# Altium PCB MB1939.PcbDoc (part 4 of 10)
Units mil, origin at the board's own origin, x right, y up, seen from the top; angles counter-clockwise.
Board outline 5910.64 x 4335.93 mil, 6 copper layers (Top Layer, l2_GND, L3_SIG, L4_VCC, L5_GND, Bottom Layer), stack 58.424 mil thick; 635 components, 489 nets, 2289 pads, 1388 vias.
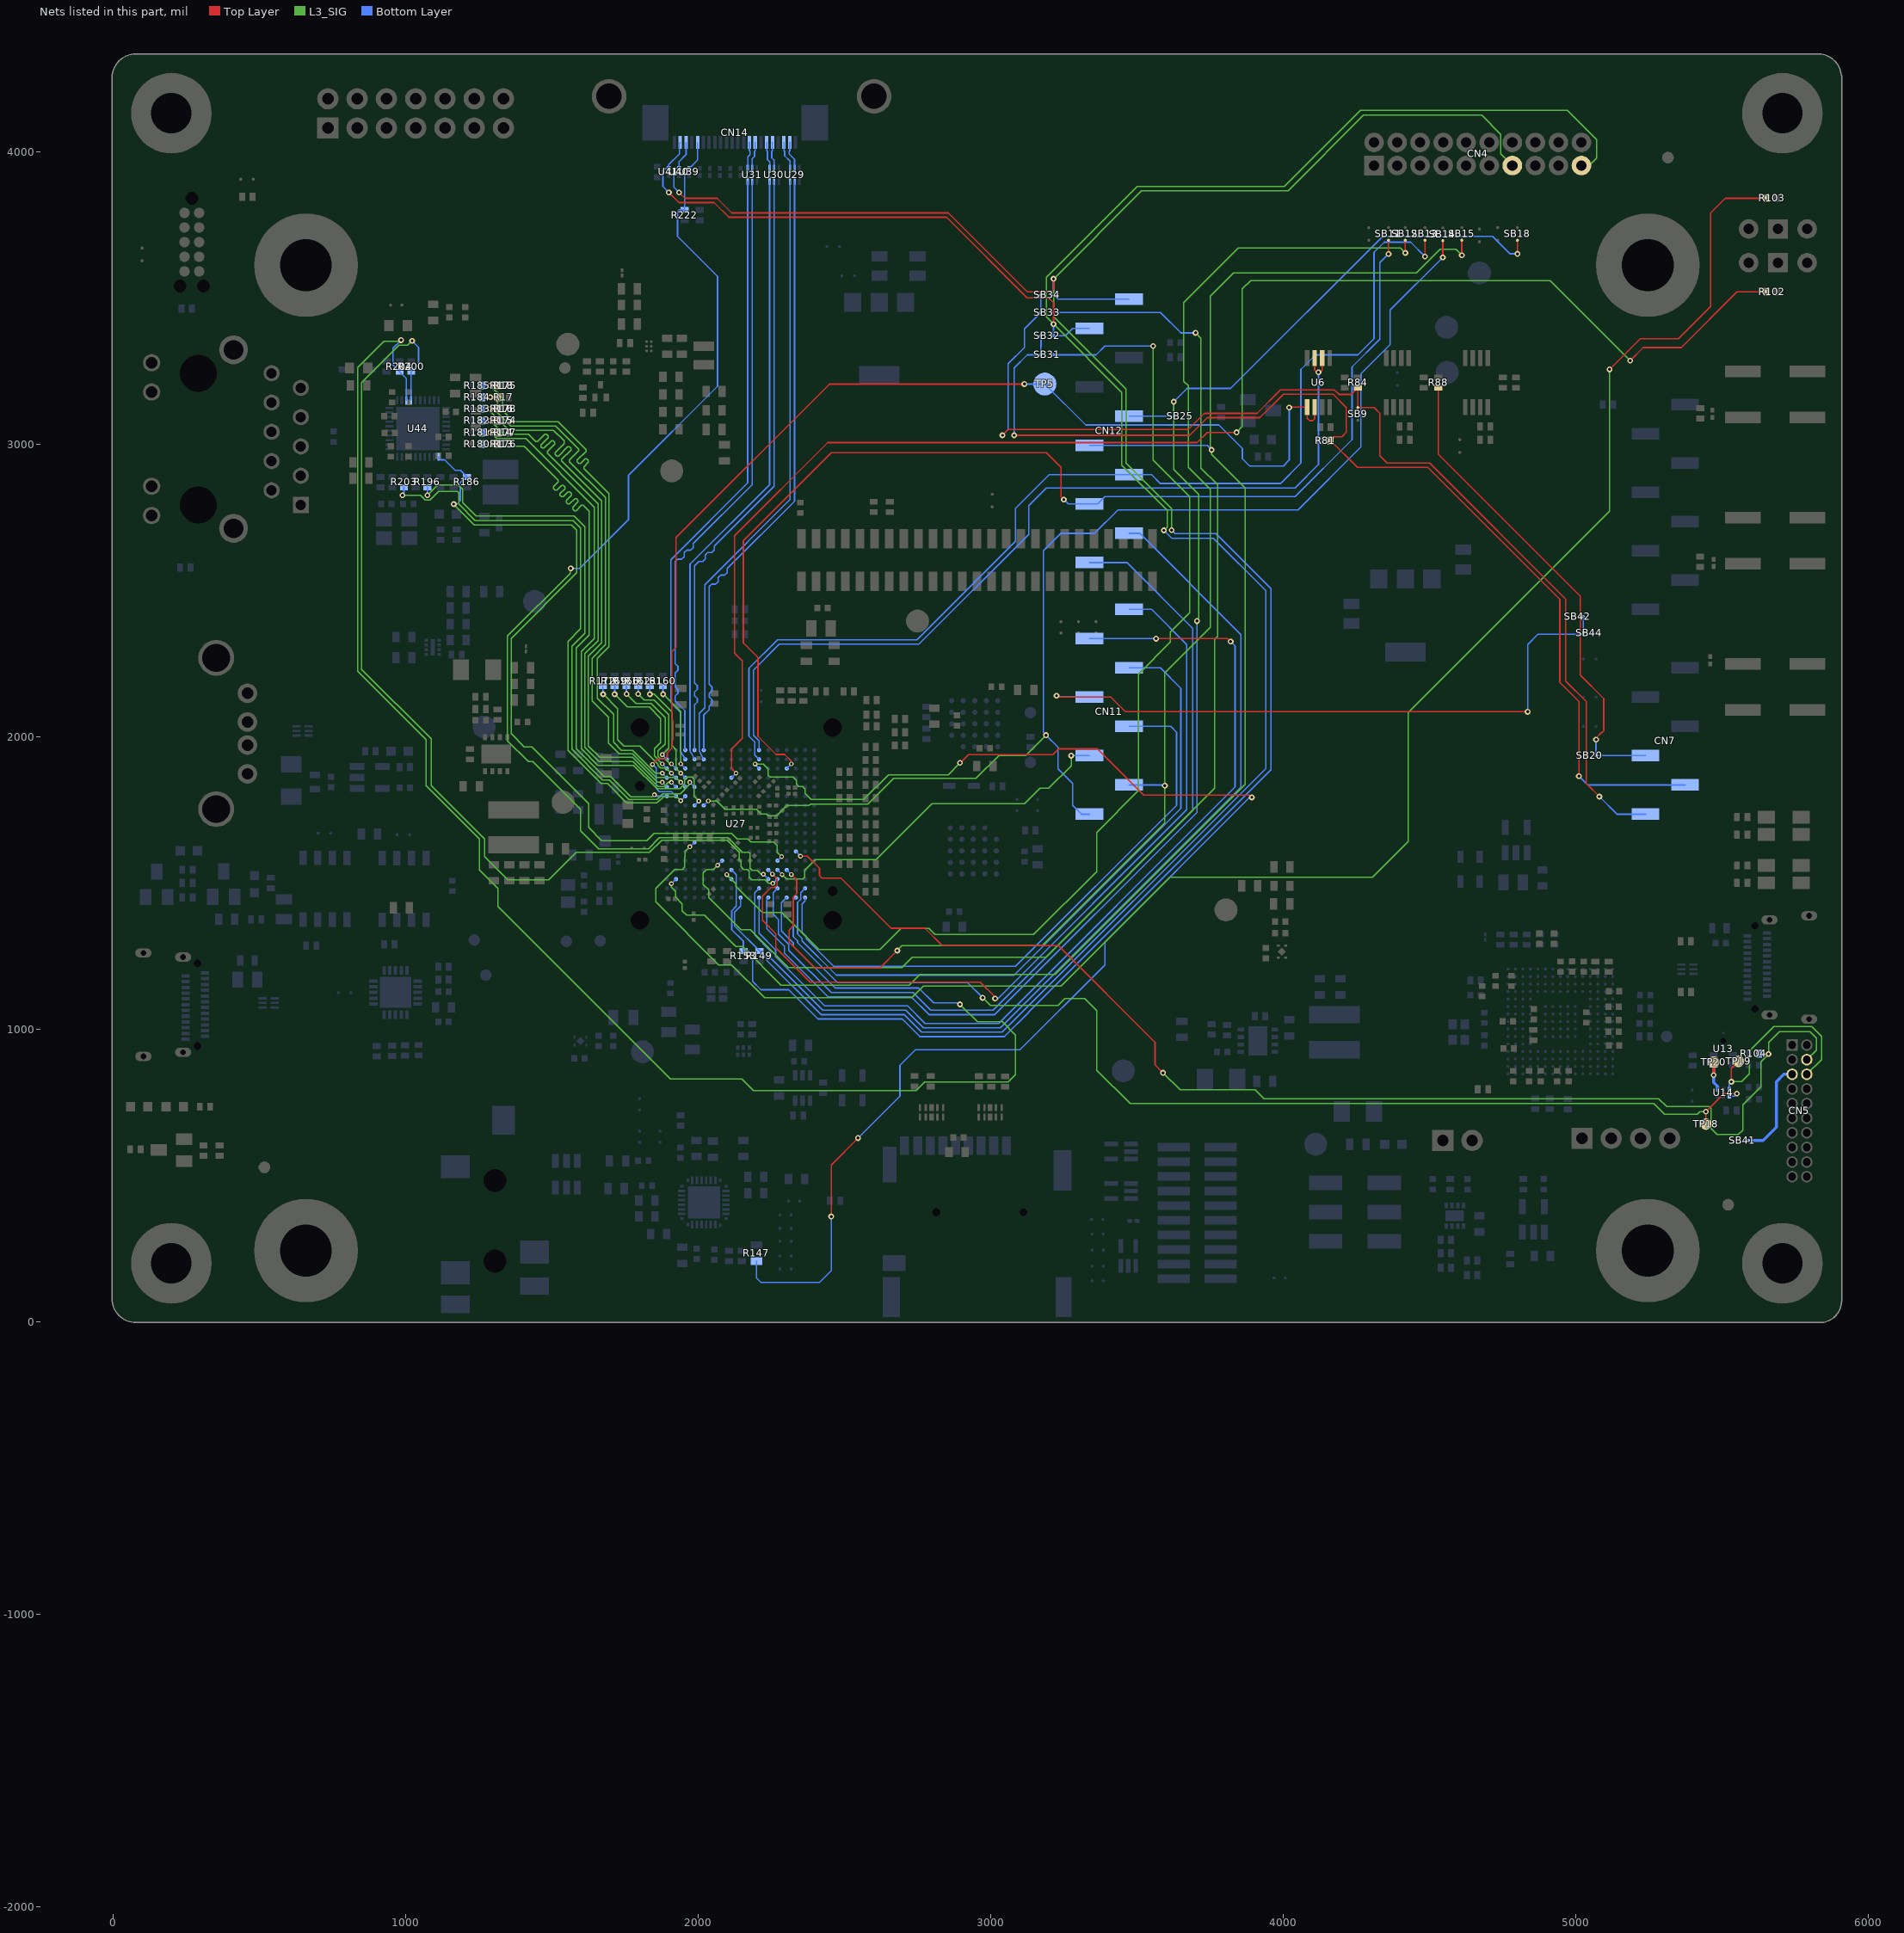
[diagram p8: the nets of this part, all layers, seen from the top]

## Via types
v1: diameter 20, hole 10, Top Layer to Bottom Layer, tented both sides, 1072 vias
v2: diameter 16, hole 8, Top Layer to Bottom Layer, tented both sides, 316 vias

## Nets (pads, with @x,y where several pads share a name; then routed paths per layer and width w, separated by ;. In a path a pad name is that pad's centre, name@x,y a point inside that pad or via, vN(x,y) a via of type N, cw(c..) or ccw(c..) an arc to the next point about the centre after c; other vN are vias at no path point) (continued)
ARD_A3R: CN7.4 R88.1 SB20.2 | length 1671.9
  Top Layer w5: R88.1@4530,3192.28 4530,2965 5015,2480 5015,2210 5095,2130 5095,2020 5090,2015 5088.62,2015 5068.62,1995 v1(5068.62,1990)
  Bottom Layer w5: SB20.2@5068.64,1935 v1(5068.62,1990) ; SB20.2@5068.64,1935 CN7.4@5237.5,1935
ARD_A4: TP5.1 U6.1 U6.2 U27.M2 | length 3802.1
  Top Layer w5: v2(1844.31,1905) 1844.31,1906.1 1861.92,1923.71 1888.24,1923.71 1894.53,1930 1894.53,1944.2 1910,1959.67 1910,1985 1914,1989 1914,2055.05 1910.31,2058.74 1910.31,2290.32 1925,2305.01 1925,2681 2449,3205 v1(3115,3205) ; v1(4020,3125) 4021.34,3126.34 U6.1@4081.61,3126.34 4081.61,3088.39 4090,3080 4100,3080 4107.2,3087.2 U6.2@4107.2,3126.34
  Bottom Layer w5: v2(1844.31,1905) 1856.73,1892.58 1856.73,1823.27 1867.7,1812.3 1909.07,1812.3 U27.M2@1924.88,1796.5 ; v1(3115,3205) TP5.1@3185,3205 3325,3065 3780,3065 3860,2985 3860,2950 3885,2925 4000,2925 4020,2945 v1(4020,3125)
ARD_A4D: SB31.1 U27.C8 | length 3857.4
  L3_SIG w4: v2(2098.08,1528.73) 2129,1497.81 2129,1489 2219.68,1398.32 2286.68,1398.32 2413,1272 2620.96,1272 2692.96,1344 2789,1344 2809.43,1323.57 3146.42,1323.57 3362.01,1539.16 3362.01,1549.1 3362,1673 3505,1816 3505,2213.97 3614,2322.97 3614,2358 3680,2424 3680,2820 3555,2945 v1(3555,3335)
  Bottom Layer w5: v2(2098.08,1528.73) U27.C8@2113.85,1513.03 U27.C8@2113.85,1513.03 ; SB31.1@3214.69,3305 3360,3305 3390,3335 v1(3555,3335)
ARD_A4R: CN7.5 R81.1 SB31.2 SB32.2 | length 3781.8
  Top Layer w5: v1(3080,3030) 3680,3030 3740,3090 3920,3090 4000,3170 4170,3170 4215,3125 4215,3040 4200,3025 4174.22,3025 R81.1@4161.23,3012.01 4253.24,2920 4493.78,2920 4945,2468.78 4945,2185 5010,2120 v1(5010,1865)
  Bottom Layer w5: v1(3080,3030) 3080,3260 3125,3305 SB31.2@3171.38,3305 3171.38,3332.5 3171.89,3333.01 3171.89,3356.99 3171.38,3357.5 SB32.2@3171.38,3370 ; v1(5010,1865) 5040,1835 CN7.5@5372.5,1835
ARD_A5: U6.6 U6.7 U27.U11 | length 2989.9
  Top Layer w5: U6.7@4107.2,3293.66 4107.2,3252.8 4115,3245 v1(4120,3245) 4125,3245 4132.8,3252.8 U6.6@4132.8,3293.66
  Bottom Layer w5: U27.U11@2208.34,1953.98 2208.34,1985.2 2189,2004.54 2189,2114.55 2189.04,2227.18 2277.66,2315.8 2754.58,2315.8 3130,2691.22 3130,2790 3190,2850 4040,2850 4120,2930 v1(4120,3245)
ARD_A5D: SB33.1 U27.E7 | length 4362.5
  L3_SIG w4: v2(2066.69,1560.41) 2052.6,1546.32 2029.29,1546.32 2017.7,1534.73 2017.7,1522.89 2017.53,1522.72 2017.53,1495.06 2036,1476.59 2036,1450.32 2146.32,1340 2178.94,1340 2307.94,1211 2696.01,1211 2731.6,1246.59 3189.36,1246.59 3765.77,1823 3765.77,2332.77 3775,2342 3775,2861 3718,2918 3718,3362 v1(3700,3380)
  Bottom Layer w5: v2(2066.69,1560.41) U27.E7@2082.35,1576.03 ; SB33.1@3214.69,3450 3580,3450 3650,3380 v1(3700,3380)
ARD_A5R: CN7.6 R84.1 SB9.1 SB33.2 SB34.2 | length 3868
  Top Layer w5: v1(3040,3030) 3060,3050 3675,3050 3730,3105 3910,3105 3990,3185 4174.66,3185 4189.88,3169.78 4232.5,3169.78 R84.1@4255,3192.28 SB9.1@4255,3124.68 4310.32,3124.68 4330,3105 4330,2960 4355,2935 4500,2935 4965,2470 4965,2190 5035,2120 5035,1840 v1(5080,1795)
  Bottom Layer w5: v1(3040,3030) 3060,3050 3060,3275 3115,3330 3115,3393.62 SB33.2@3171.38,3450 SB34.2@3171.38,3510 ; v1(5080,1795) 5140,1735 CN7.6@5237.5,1735
ARD_D0: CN11.1 SB14.1 U27.L5 | length 4346.3
  Top Layer w5: v1(4545,3638) SB14.1@4545,3695.32
  L3_SIG w4: v2(2034.68,1780.32) 2064.68,1780.32 2093,1752 2199,1752 2216,1735 2233,1735 2239,1729 2269.02,1729 2304.42,1764.4 2379.4,1764.4 2385,1770 2580.02,1770 2668.02,1858 2950.02,1858 3028.02,1936 3120.02,1936 v1(3189,2005)
  Bottom Layer w5: U27.L5@2019.36,1765 v2(2034.68,1780.32) ; CN11.1@3337.5,1735 3310,1735 3280,1765 3280,1840 3230,1890 3230,1964 v1(3189,2005) 3180,2014 3180,2635 3240,2695 3355,2695 3435,2775 4050,2775 4265,2990 4265,3240 4365,3340 4365,3458 v1(4545,3638)
ARD_D1: CN11.2 SB12.1 U27.D14 | length 4686.2
  Top Layer w5: v2(2318.52,1528.8) 2337.1,1510.22 2337.1,1463.83 2325.28,1452.01 2325.28,1352.94 2311.06,1338.72 2311.06,1297.36 2399.42,1209 2621,1209 v1(2680.78,1268.78) ; v1(4416.81,3653.19) SB12.1@4416.81,3696.38
  L3_SIG w4: v1(2680.78,1268.78) 2697,1285 3175,1285 3595,1705 v1(3595,1832.5) 3595,2218.02 3750,2373.02 3750,2845 3675,2920 3675,3200 3660,3215 3660,3484 3846,3670 4400,3670 v1(4416.81,3653.19)
  Bottom Layer w5: U27.D14@2302.83,1544.53 v2(2318.52,1528.8) ; CN11.2@3472.5,1835 3592.5,1835 v1(3595,1832.5)
ARD_D2: CN11.3 U27.D13 | length 1288.6
  L3_SIG w4: v2(2286.99,1528.8) 2302.79,1513 2359,1513 2364.8,1518.8 2364.8,1542.8 2401,1579 2608,1579 2800,1771 3116.01,1771 3168.02,1823.01 3198.01,1823.01 3275,1900 v1(3275,1935)
  Bottom Layer w5: U27.D13@2271.33,1544.53 U27.D13@2271.33,1544.53 v2(2286.99,1528.8) ; v1(3275,1935) CN11.3@3337.5,1935
ARD_D3: CN11.4 U27.A16 | length 2104.6
  Bottom Layer w5: U27.A16@2365.82,1450.04 2365.82,1438.86 2355,1428.04 2355,1331.22 2370,1316.22 2370,1308.44 2463.44,1215 3085,1215 3635,1765 3635,2015 3615,2035 CN11.4@3472.5,2035
ARD_D4: CN11.5 SB42.1 SB44.1 | length 2237.5
  Top Layer w5: v1(3225,2140) 3230,2135 3410,2135 3460,2085 v1(4835,2085)
  Bottom Layer w5: v1(3225,2140) 3230,2135 CN11.5@3337.5,2135 ; v1(4835,2085) 4835,2315 4870,2350 5025,2350 ; SB42.1@5025,2410 5025,2356.61 SB44.1@5026.61,2355
ARD_D5: CN11.6 U27.B16 | length 2392.4
  Bottom Layer w5: U27.B16@2365.82,1481.54 2350.74,1466.46 2350.74,1444.12 2340,1433.38 2340,1325 2355,1310 2355,1302.22 2472.22,1185 3080,1185 3650,1755 3650,2165 3580,2235 CN11.6@3472.5,2235
ARD_D6: CN11.7 U27.A11 | length 3214.7
  Top Layer w5: v1(3565,2335) 3810,2335 v1(3820,2325)
  Bottom Layer w5: 2208.32,1417.4 2208.32,1327.9 2265,1271.22 2265,1247.56 2432.56,1080 2716.34,1080 2776.34,1020 3026.88,1020 3835,1828.12 3835,2310 v1(3820,2325) ; 2208.34,1417.42 U27.A11@2208.34,1450.04 ; CN11.7@3337.52,2335 v1(3565,2335)
ARD_D7: CN11.8 U27.D12 | length 2883.8
  Top Layer w5: v2(2254.18,1530.18) 2270,1514.36 2270,1504.43 ; 2270.02,1504.41 2270.02,1492.39 2261.53,1483.9 2248.75,1483.9 2220,1455.15 2220,1372.28 2266.06,1326.22 2266.06,1278.7 2383.76,1161 2964,1161 3015,1110 v1(3015,1105)
  Bottom Layer w5: U27.D12@2239.84,1544.53 v2(2254.18,1530.18) ; v1(3015,1105) 3025,1105 3670,1750 3670,2315 3550,2435 CN11.8@3472.48,2435
ARD_D8: CN12.1 U27.B13 | length 3055.8
  Bottom Layer w5: U27.B13@2271.33,1481.54 U27.B13@2271.33,1481.54 2256.72,1466.99 2256.72,1393.37 2275,1374.62 2275,1324.88 2310,1289.88 2310,1270 2455,1125 2735,1125 2795,1065 3008.22,1065 3690,1746.78 3690,2370 3465,2595 CN12.1@3337.5,2595
ARD_D9: CN12.2 U27.B11 | length 3361.2
  Bottom Layer w5: U27.B11@2208.34,1481.54 U27.B11@2208.34,1481.54 2193.32,1466.58 2193.32,1321.68 2250,1265 2250,1241.34 2426.34,1065 2710.12,1065 2770.12,1005 3033.1,1005 3855,1826.9 3855,2349 3509,2695 CN12.2@3472.5,2695
ARD_D10: CN12.3 SB11.1 U27.R14 | length 4029.9
  Top Layer w5: v2(2318.47,1906.76) 2318.47,1916.52 2295.98,1939.01 2266.52,1939.01 2204.52,2001.01 2204.52,2270.48 2155,2320 2155,2670 2455,2970 3190,2970 3240,2920 3240,2820 v1(3250,2810) ; v1(4359.49,3649.49) SB11.1@4359.49,3696.38
  Bottom Layer w5: U27.R14@2302.83,1890.99 2302.82,1891.11 v2(2318.47,1906.76) ; v1(3250,2810) 3265,2795 CN12.3@3337.5,2795 3365,2795 3390,2820 4040,2820 4235,3015 4235,3263.78 4330,3358.78 4330,3620 v1(4359.49,3649.49)
ARD_D11: CN12.4 SB13.1 U27.T11 | length 3765.5
  Top Layer w5: v1(4484.13,3640.87) SB13.1@4484.13,3696.38
  Bottom Layer w5: U27.T11@2208.34,1922.48 2193.72,1937.1 2193.72,1981.84 2174,2001.49 2174,2105.71 2174.04,2233.4 2271.44,2330.8 2748.36,2330.8 3085,2667.44 3085,2780 3200,2895 CN12.4@3472.5,2895 3550,2895 3580,2865 3990,2865 4060,2935 4060,3255 4110,3305 4255,3305 4310,3360 4310,3655 4345,3690 4435,3690 v1(4484.13,3640.87)
ARD_D12: CN12.5 SB15.1 U27.C2 | length 5570.7
  Top Layer w5: v1(4610,3645) SB15.1@4610,3696.7
  L3_SIG w4: v2(1909.12,1497.3) 1909.12,1485.5 1923.02,1471.6 1923.02,1451.98 1946,1429 1946,1405 1961,1390 2021,1390 2129,1282 2152.04,1282 2283.04,1151 2721.95,1151 2757.54,1186.59 3219.26,1186.59 3870,1837.33 3870,2850 3755,2965 v1(3755,2980) 3750,2985 3750,3505 3830,3585 4455,3585 4535,3665 4590,3665 v1(4610,3645)
  Bottom Layer w5: v2(1909.12,1497.3) U27.C2@1924.85,1513.03 ; CN12.5@3337.5,2995 3740,2995 v1(3755,2980)
ARD_D13: CN12.6 SB18.1 SB25.1 U27.A12 | length 5124.4
  Top Layer w5: v1(4799.84,3650) SB18.1@4799.84,3696.38
  L3_SIG w4: v1(3625.32,3144.68) 3625.32,2913.42 3711,2827.74 3711,2401 v1(3705,2395)
  Bottom Layer w5: U27.A12@2239.84,1450.04 2235,1445.21 2235,1343.66 2295,1283.66 2295,1260 2445,1110 2728.78,1110 2788.78,1050 3014.44,1050 3705,1740.56 v1(3705,2395) ; CN12.6@3472.5,3095 SB25.1@3625.33,3095 v1(3625.32,3144.68) ; v1(3625.32,3144.68) 3670.64,3190 3820,3190 4340,3710 4715,3710 4775,3650 v1(4799.84,3650)
ARD_D14: CN4.10 CN12.9 CN14.21 R149.2 SB32.1 U27.A9 U41.1 | length 8751.9
  Top Layer w5: v1(1900,3860) 1935,3825 2055,3825 2105,3775 2849.68,3775 3124.68,3500 3198.11,3500 3214.68,3483.43 v1(3214.68,3410)
  L3_SIG w4: v1(3592,2705) 3603,2716 3603,2773 3448,2928 3448,3176.68 v1(3214.68,3410) 3190,3434.68 3190,3570 3500,3880 4004,3880 4264,4140 4970,4140 5070.1,4039.9 5070.1,3977.66 CN4.10@5018.7,3926.26
  Bottom Layer w5: v1(1900,3860) 1880,3880 1880,3934 1888.31,3942.31 U41.1@1900,3942.31 1900,3955 1936.11,3991.11 1936.11,4027.52 CN14.21@1939.3,4030.71 ; U27.A9@2145.35,1450.04 2145.34,1436.38 2145.62,1436.1 2145.62,1420.62 2125,1400 2125,1352.72 R149.2@2210,1267.72 2211.06,1267.72 2234.99,1243.79 2234.99,1235.13 2420.12,1050 2703.9,1050 2763.9,990 3039.32,990 3940,1890.68 3940,2499 3761,2678 3619,2678 v1(3592,2705) ; v1(3214.68,3410) SB32.1@3214.69,3370 3255,3370 3280,3395 CN12.9@3337.52,3395
ARD_D15: CN4.7 CN12.10 CN14.20 R153.2 SB34.1 U27.D8 U40.1 | length 8620.7
  Top Layer w5: v1(1935,3860) 1955,3840 2065,3840 2115,3790 2855,3790 3125,3520 3205,3520 3214.68,3529.68 v1(3214.68,3564.68)
  L3_SIG w4: v1(3618,2706) 3618,2779 3462,2935 3462,3187.68 3215,3434.68 3215,3564.36 v1(3214.68,3564.68) 3516,3866 4016,3866 4274,4124 4678.05,4124 4743.12,4058.93 4743.12,3991.33 CN4.7@4782.49,3951.97
  Bottom Layer w5: v1(1935,3860) 1917.02,3877.98 1917.02,3937.02 1922.31,3942.31 U40.1@1935,3942.31 1935,3965 1958.98,3988.98 CN14.20@1958.98,4030.71 ; U27.D8@2113.85,1544.53 2130.62,1527.76 2130.62,1420.62 2115,1405 2115,1340 2155,1300 R153.2@2155,1267.72 2171.28,1267.72 2186.5,1252.5 2186.5,1163.5 2215,1135 2310,1135 2410,1035 2697.68,1035 2757.68,975 3047.07,975 3130,1057.93 3130,1059 3958,1887 3958,2506 3770,2694 3630,2694 v1(3618,2706) ; v1(3214.68,3564.68) SB34.1@3214.69,3510 3229.68,3495 CN12.10@3472.48,3495
AUDIO_INT: R147.2 U27.R11 | length 4700.7
  Top Layer w5: v1(2455,360) 2455,536.22 v1(2546.75,627.97) ; v1(2895,1910.33) 2896.33,1910.33 2924,1938 3212,1938 3232,1958 3365,1958 3523,1800 3885,1800 v1(3892.5,1792.5)
  L3_SIG w4: v2(2194.63,1906.63) 2223.37,1906.63 2240,1890 2240,1868 2246.79,1861.21 2292.78,1861.21 2292.84,1861.27 2324.73,1861.27 2336.02,1849.98 2336.02,1837.9 2344.22,1829.7 2356.3,1829.7 2365,1821 2365,1806 2386,1785 2566,1785 2651,1870 2854.67,1870 v1(2895,1910.33)
  Bottom Layer w5: v2(2194.63,1906.63) 2194.63,1904.7 U27.R11@2208.34,1890.99 ; R147.2@2200,207.44 2200,150 2215,135 2415,135 2455,175 v1(2455,360) ; v1(2546.75,627.97) 2690,771.22 2690,877 2743,930 3100,930 3390,1220 3390,1297.78 3885.07,1792.85 3892.15,1792.85 v1(3892.5,1792.5)
BOOT0: R103.2 U27.G4 | length 6067.6
  Top Layer w5: v1(5115,3255) 5220,3360 5350,3360 5460,3470 5460,3790 5510,3840 R103.2@5652.28,3840
  L3_SIG w4: v2(1972.09,1623.23) 1955.86,1607 1955.86,1587.86 1954.6,1586.6 1954.6,1554.52 1946.4,1546.32 1921,1546.32 1855.89,1481.21 1855.89,1480.89 1855,1480 1855,1435 2070,1220 2115,1220 2227,1108 2729.98,1108 2769.98,1148 3241,1148 3613,1520 4305,1520 4427,1642 4427,2082 5115,2770 v1(5115,3255)
  Bottom Layer w5: v2(1972.09,1623.23) U27.G4@1987.87,1639.02
BOOT1: R102.2 U27.P8 | length 5240.5
  Top Layer w5: v2(2129.68,1875.32) 2113.98,1891.02 2113.98,1957.07 2151,1994.09 2151,2259 2125,2285 2125,2687 2443,3005 3705,3005 3739.88,3039.88 v1(3840,3039.88) ; v1(5185,3285) 5230,3330 5360,3330 5550,3520 R102.2@5652.28,3520
  L3_SIG w4: v1(3840,3039.88) 3860,3059.88 3860,3530 3888,3558 4912,3558 v1(5185,3285)
  Bottom Layer w5: U27.P8@2113.85,1859.49 v2(2129.68,1875.32)
CK: CN5.4 R104.2 U27.F15 | length 4389.6
  Top Layer w5: v2(2350.02,1591.8) 2373.2,1591.8 2415,1550 2415,1525 2423.49,1516.51 2488.49,1516.51 2660,1345 2774.99,1345 2834.67,1285.32 3231.48,1285.32 3561.4,955.4 3561.4,878.6 v1(3589,851)
  L3_SIG w4: v1(3589,851) 3647,793 3904,793 3934,763 5283,763 5310,736 5456,736 5462,730 5462,660.5 5482.82,639.68 5554.69,639.68 5570,655 5570,741.85 5632,803.85 5632,889 v1(5658,915) 5658,955 5695,992 5800,992 5822,970 5822,929.18 CN5.4@5788.72,895.9
  Bottom Layer w5: U27.F15@2334.33,1607.52 v2(2350.02,1591.8) ; R104.2@5625.1,916.51 5656.49,916.51 v1(5658,915)
CSI_CKN: U27.U3 U31.5 | length 2101.2
  Bottom Layer w5.1: U27.U3@1956.37,1953.98 1955,1955.35 1955,2089 1921.8,2122.2 1921.8,2139.1 1931.6,2148.9 1931.6,2160.9 1921.8,2170.7 1921.8,2217.7 1931.6,2227.5 1931.6,2239.5 1921.8,2249.3 1921.8,2598.08 1930.28,2606.56 1944.15,2606.56 1952.63,2615.05 1952.63,2628.91 1961.11,2637.39 1974.98,2637.39 1983.46,2645.88 1983.46,2659.74 2184.62,2860.9 2184.62,3874.39 2185,3874.77 U31.5@2185,3899.33
CSI_CKP: U27.T3 U31.6 | length 2104.1
  Bottom Layer w5.1: U27.T3@1956.37,1922.48 1940,1950.3 1940,2082.78 1906.8,2115.98 1906.8,2604.3 2169.62,2867.12 2169.62,3879.63 2169.25,3880 U31.6@2169.25,3899.33
CSI_CLK_N_CON: CN14.8 U31.2 | length 94.3
  Bottom Layer w5.1: U31.2@2185,3940.67 2185,3975 2192.85,3982.85 2192.85,3999.87 2195.2,4002.22 CN14.8@2195.2,4030.71
CSI_CLK_P_CON: CN14.9 U31.1 | length 94.6
  Bottom Layer w5.1: U31.1@2169.25,3940.67 2169.25,3945.67 2170,3946.42 2170,3981.22 2177.85,3989.07 2177.85,3999.87 2175.51,4002.21 CN14.9@2175.52,4030.71
CSI_D0_N: U27.U5 U29.5 | length 2106.6
  Bottom Layer w5.1: U27.U5@2019.36,1953.98 2019.3,1954.04 2019.3,2073.3 2037.9,2091.9 2037.9,2103.9 2047.7,2113.7 2047.7,2125.7 2037.9,2135.5 2037.9,2147.5 2047.7,2157.3 2047.7,2169.3 2037.9,2179.1 2037.9,2512.9 2046.38,2521.38 2060.25,2521.38 2068.73,2529.87 2068.73,2543.73 2077.21,2552.21 2091.08,2552.21 2099.56,2560.7 2099.56,2574.56 2329.62,2804.62 2329.62,3874.39 2330,3874.77 U29.5@2330,3899.33
CSI_D0_N_CON: CN14.2 U29.2 | length 98.9
  Bottom Layer w5.1: CN14.2@2313.31,4030.71 2313.31,4002.22 2310.96,3999.87 2310.96,3991.49 2329.62,3972.83 2329.62,3941.05 U29.2@2330,3940.67
CSI_D0_P: U27.T5 U29.6 | length 2109.4
  Bottom Layer w5.1: U27.T5@2019.36,1922.48 2004.3,1950.3 2004.3,2079.52 2022.9,2098.12 2022.9,2519.12 2314.62,2810.84 2314.62,3874.39 2314.25,3874.76 U29.6@2314.25,3899.33
CSI_D0_P_CON: CN14.3 U29.1 | length 98.9
  Bottom Layer w5.1: CN14.3@2293.63,4030.71 2293.62,4002.21 2295.96,3999.87 2295.96,3985.27 2314.62,3966.61 2314.62,3941.04 U29.1@2314.25,3940.67
CSI_D1_N: U27.U4 U30.5 | length 2090.6
  Bottom Layer w5.1: U27.U4@1987.87,1953.98 1987.8,1954.04 1987.8,2108.7 1997.6,2118.5 1997.6,2130.5 1987.8,2140.3 1987.8,2152.3 1997.6,2162.1 1997.6,2174.1 1987.8,2183.9 1987.8,2584.08 2002.08,2598.36 2015.95,2598.36 2024.44,2606.85 2024.44,2620.72 2032.92,2629.2 2046.79,2629.2 2055.27,2637.69 2055.27,2651.55 2259.62,2855.9 2259.62,3874.39 2260,3874.77 U30.5@2260,3899.33
CSI_D1_N_CON: CN14.5 U30.2 | length 94.4
  Bottom Layer w5.1: CN14.5@2254.25,4030.71 2254.25,4002.21 2251.91,3999.87 2251.91,3978.09 2260,3970 U30.2@2260,3940.67
CSI_D1_P: U27.T4 U30.6 | length 2094
  Bottom Layer w5.1: U27.T4@1987.87,1922.48 1977.44,1943.25 1972.85,1947.84 1972.85,1952.4 1972.8,1952.5 1972.8,2590.3 2244.62,2862.12 2244.62,3874.39 2244.25,3874.76 U30.6@2244.25,3899.33
CSI_D1_P_CON: CN14.6 U30.1 | length 94.7
  Bottom Layer w5.1: CN14.6@2234.57,4030.71 2234.57,4002.21 2236.91,3999.87 2236.91,3971.87 2245,3963.78 2245,3941.42 U30.1@2244.25,3940.67
D1: TP18.1 U14.4 U27.A15 | length 3857.5
  Top Layer w5: TP18.1@5444,676 v1(5444,718) 5506,780 v1(5550,780)
  L3_SIG w4: v1(2972.5,1107.5) 2999,1081 3230,1081 3254,1105 3321,1105 3363,1063 3363,860 3477,746 5266,746 5303,709 5414.66,709 5423.66,718 v1(5444,718)
  Bottom Layer w5: U27.A15@2334.33,1450.04 2325,1440.72 2325,1317.32 2340,1302.32 2340,1296 2476,1160 2920,1160 v1(2972.5,1107.5) ; U14.4@5523.53,771.35 5541.35,771.35 v1(5550,780)
D2: CN5.5 SB41.1 | length 318.3
  Bottom Layer w10: 5605,620 5640,620 5685,665 5685,820.34 5710.56,845.9 CN5.5@5738.72,845.9
Data_Con: CN5.6 TP19.1 U14.3 | length 706
  Top Layer w5: v1(5531.18,820.52) 5531.18,865.33 TP19.1@5555.85,890
  L3_SIG w4: v1(5531.18,820.52) 5566.52,820.52 5593,847 5593,926 5677,1010 5805,1010 5839,976 5839,896.18 CN5.6@5788.72,845.9
  Bottom Layer w5: U14.3@5523.53,794.97 5523.53,812.87 v1(5531.18,820.52)
Data_Mems: TP20.1 U13.1 U14.1 | length 135
  Top Layer w10: v1(5470.69,843) 5471,843.31 TP20.1@5471,888
  Bottom Layer w10: U13.1@5470.69,879.3 v1(5470.69,843) 5470.69,818.28 5484.16,804.81 U14.1@5484.16,794.97
EN_MODULE: CN14.18 R222.2 U27.C12 U39.1 | length 3651.7
  L3_SIG w4: v1(1565,2575) 1562.5,2572.5 1562.5,2557.5 1349,2344 1349,1986 1419.99,1915.01 1435,1915.01 1599.01,1751 1599.01,1678 1660.18,1616.83 1830.03,1616.83 1867.2,1654 2102.32,1654 2151.32,1605 2173.21,1605 2177.21,1601 2177.21,1549.8 2184.21,1542.8 2202.2,1542.8 2215.57,1529.43 v2(2223.01,1529.43)
  Bottom Layer w5: v1(1565,2575) 1595,2575 1762.5,2742.5 1762.5,2893.48 2066.6,3197.58 2066.6,3573 1930,3709.6 1930,3795 1935,3800 R222.2@1954.02,3800 1954.02,3936.32 1960,3942.3 U39.1@1970,3942.31 1998.35,3970.65 CN14.18@1998.35,4030.71 ; v2(2223.01,1529.43) v2@2223.43,1529.43 ; v2@2223.44,1529.43 U27.C12@2239.84,1513.03
ETH_CLK: R203.2 U27.M3 | length 2006.3
  L3_SIG w4: v1(990,2825) 1050.81,2825 1050.88,2825.07 1067.95,2808 1083.13,2808 1112.95,2837.82 1177.18,2837.82 1182,2833 1182,2794.76 1238.76,2738 1573.75,2738 1599,2712.75 1599,2369 1555,2325 1555,1953.35 1669.18,1839.17 1690.79,1839.17 1755.96,1774 1859.12,1774 1862.72,1777.6 1864.39,1777.6 1881.79,1795 1927,1795 v2(1941,1781)
  Bottom Layer w5: v1(990,2825) 995,2830 R203.2@995,2852.28 ; v2(1941,1781) 1942,1782 1942,1782.13 U27.M3@1956.37,1796.5
ETH_CLK125: R196.1 U27.N4 | length 1968.3
  L3_SIG w4: v1(1075,2825) 1110,2860 1180,2860 1195,2845 1195,2800 1241,2754 1576,2754 1613,2717 1613,2353 1568.4,2308.4 1568.4,1966.89 1568.39,1956.94 1673.68,1851.65 1696.35,1851.65 1762.5,1785.5 1859.3,1785.5 1878.9,1805.1 1939.09,1805.1 1972.02,1838.03 v2(1972.02,1843.7)
  Bottom Layer w5: v1(1075,2825) R196.1@1075,2852.28 ; v2(1972.02,1843.7) 1987.73,1827.99 U27.N4@1987.87,1827.99
ETH_GTX_CLK: R160.1 U27.R3 | length 313
  L3_SIG w4: v1(1880.52,2145) 1940.51,2085.01 v2(1940.51,1906.71)
  Bottom Layer w5: R160.1@1880,2172.28 1880,2145.52 v1(1880.52,2145) ; v2(1940.51,1906.71) 1956.23,1890.99 U27.R3@1956.37,1890.99
ETH_MDC: R204.1 U27.A14 U44.13 | length 5726
  L3_SIG w4: v1(985,3355) 980.84,3350.84 925.83,3350.84 837.08,3262.09 837.08,2222.92 1070,1990 1070,1832.88 1253,1649.88 1253,1544.88 1316,1481.88 1316,1420 1906,830 2150,830 2190,790 2745,790 2775,820 3060,820 3085,845 3085,980 3040,1025 2955,1025 v1(2895,1085)
  Bottom Layer w5: v1(985,3355) 957.5,3327.5 957.5,3269.78 1003.26,3224.02 U44.13@1003.27,3149.29 ; U27.A14@2302.83,1450.04 2285,1432.22 2285,1336.1 2325,1296.1 2325,1285 2469,1141 2754,1141 2805,1090 2890,1090 v1(2895,1085)
ETH_MDINT: R186.1 U27.E13 U44.31 | length 2694
  L3_SIG w4: v1(1165,2794.72) 1165,2793.51 1235.51,2723 1567.46,2723 1585,2705.46 1585,2560 1361,2336 1361,2009.94 1405.94,1965 1432,1965 1626,1771 1626,1690 1671,1645 1824,1645 1849,1670 2114,1670 2134,1650 2170,1650 2180,1640 2258.62,1640 2261.61,1637.01 ; 2261.66,1637.01 2269.86,1628.81 ; 2269.86,1628.76 2270.66,1627.96 2270.66,1605.34 v2(2285.65,1590.35)
  Bottom Layer w5: U44.31@1113.5,2956.37 1113.5,2951.5 1119.01,2945.99 1134.01,2945.99 1170,2910 1187.72,2910 R186.1@1210,2887.72 1206.26,2887.72 1187.5,2868.96 1187.5,2806.5 1175.72,2794.72 v1(1165,2794.72) ; U27.E13@2271.33,1576.03 v2(2285.65,1590.35)
ETH_MDIO: R200.1 U27.C13 U44.14 | length 3444.6
  L3_SIG w4: v1(1022.72,3352.72) 1008,3338 978,3338 850,3210 850,2230 1087.5,1992.5 1087.5,1832.35 1270,1649.85 1270,1590 1350,1510 1490,1510 1584.17,1604.17 1834.17,1604.17 1876,1646 2098.99,1646 2141,1603.99 2141,1579 2146,1574 2146,1555.52 2155.22,1546.3 2168.1,1546.3 2175.02,1539.38 2175.02,1518.98 2182.7,1511.3 2228.49,1511.3 2241.39,1498.4 v2(2255.52,1498.4)
  Bottom Layer w5: U44.14@1019.01,3149.29 1019.01,3246.29 1045,3272.28 1045,3330.44 v1(1022.72,3352.72) ; v2(2255.52,1498.4) 2256.7,1498.4 U27.C13@2271.33,1513.03
ETH_RX_CLK: R13.2 R176.1 R180.1 U27.M1 | length 1949.3
  Top Layer w5: v1(1290,3000) R13.2@1317.28,3000
  L3_SIG w4: v1(1290,3000) 1298,2992 1406,2992 1522.18,2875.82 1522.18,2870.16 1505.84,2853.82 1505.84,2848.16 1511.5,2842.5 1517.16,2842.5 1533.5,2858.84 1539.16,2858.84 1544.82,2853.18 1544.82,2847.52 1528.48,2831.18 1528.48,2825.52 1534.14,2819.86 1539.8,2819.86 1556.14,2836.2 1561.8,2836.2 1567.46,2830.54 1567.46,2824.88 1549.12,2806.54 1549.12,2800.88 1554.78,2795.22 1560.44,2795.22 1578.78,2813.56 1584.44,2813.56 1590.1,2807.9 1590.1,2802.24 1571.76,2783.9 1571.76,2778.24 1577.42,2772.58 1583.08,2772.58 1601.42,2790.92 1607.08,2790.92 1628,2770 1628,2347.6 1584,2303.6 1584,1958.31 1678.66,1863.65 1701.35,1863.65 1770.1,1794.9 1844.4,1794.9 v2(1850.6,1801.1)
  Bottom Layer w5: R180.1@1262.72,3000 v1(1290,3000) R176.1@1317.28,3000 ; v2(1850.6,1801.1) 1855.2,1796.5 U27.M1@1893.38,1796.5
ETH_RX_DV: R14.2 R177.1 R181.1 U27.L4 | length 1961.3
  Top Layer w5: v1(1290,3040) R14.2@1317.28,3040
  L3_SIG w4: v1(1290,3040) 1311,3019 1411,3019 1646,2784 1646,2336 1601,2291 1601,1958.29 1657.29,1902 1779,1902 1859.3,1821.7 1938.32,1821.7 1954.52,1837.9 1954.52,1853.92 1961.8,1861.2 1979.7,1861.2 1986.02,1854.88 1986.02,1796.84 v2(2002.86,1780)
  Bottom Layer w5: R181.1@1262.72,3040 v1(1290,3040) R177.1@1317.28,3040 ; U27.L4@1987.87,1765 v2(2002.86,1780)
ETH_RXD0: R15.2 R174.1 R182.1 U27.N2 | length 1955
  Top Layer w5: v1(1290,3080) R15.2@1317.28,3080
  L3_SIG w4: v1(1290,3080) 1337,3033 1421,3033 1445.49,3008.51 1451.15,3008.51 1476.49,3033.85 1482.15,3033.85 1487.81,3028.19 1487.81,3022.53 1462.47,2997.19 1462.47,2991.53 1468.13,2985.87 1473.79,2985.87 1499.13,3011.21 1504.79,3011.21 1510.45,3005.55 1510.45,2999.89 1485.11,2974.55 1485.11,2968.89 1658.5,2795.5 1658.5,2328.5 1613.4,2283.4 1613.4,1962.87 1661.27,1915 1778,1915 1863.3,1829.7 1884.71,1829.7 1898.71,1843.7 v2(1909.03,1843.7)
  Bottom Layer w5: R182.1@1262.72,3080 v1(1290,3080) R174.1@1317.29,3080 ; v2(1909.03,1843.7) 1924.74,1827.99 U27.N2@1924.88,1827.99
ETH_RXD1: R16.2 R178.1 R183.1 U27.N1 | length 1947.3
  Top Layer w5: v1(1290,3120) R16.2@1317.28,3120
  L3_SIG w4: v1(1290,3120) 1290,3111 1354,3047 1506,3047 1542,3011 1542,3000.94 1511.36,2970.3 1511.36,2964.64 1517.02,2958.98 1522.68,2958.98 1554.02,2990.32 1560.68,2990.32 1565.84,2985.16 1565.84,2979.5 1534,2947.66 1534,2942 1671,2805 1671,2321 1625.4,2275.4 1625.4,1967.85 1664.25,1929 1776,1929 1861.3,1843.7 v2(1877.53,1843.7)
  Bottom Layer w5: R183.1@1262.72,3120 v1(1290,3120) R178.1@1317.28,3120 ; v2(1877.53,1843.7) 1893.24,1827.99 U27.N1@1893.38,1827.99
ETH_RXD2: R17.2 R184.1 U27.N3 | length 1891.9
  Top Layer w5: v1(1290,3160) R17.2@1317.28,3160
  L3_SIG w4: v1(1290,3160) 1307,3160 1315,3152 1315,3107 1360,3062 1513,3062 1592.18,2982.82 1592.18,2977.16 1560.34,2945.32 1560.34,2939.66 1683,2817 1683,2314 1637.4,2268.4 1637.4,2122.2 1693.8,2065.8 1693.8,1978.55 1731.35,1941 1776,1941 1856.35,1860.65 1923.57,1860.65 v2(1940.52,1843.7)
  Bottom Layer w5: R184.1@1262.72,3160 v1(1290,3160) ; v2(1940.52,1843.7) 1956.23,1827.99 U27.N3@1956.37,1827.99
ETH_RXD3: R18.2 R175.1 R185.1 U27.P1 | length 1906.8
  Top Layer w5: v1(1290,3200) R18.2@1317.28,3200
  L3_SIG w4: v1(1290,3200) 1332,3158 1332,3114 1370,3076 1522,3076 1617.14,2980.86 1617.14,2975.2 1586.8,2944.86 1586.8,2939.2 1592.46,2933.54 1598.12,2933.54 1613.96,2949.38 1619.62,2949.38 1625.28,2943.72 1625.28,2938.06 1609.44,2922.22 1609.44,2916.56 1695,2831 1695,2307 1655.4,2267.4 1655.4,2131.5 1710.8,2076.1 1710.8,1980.5 1738.3,1953 1776,1953 1853.8,1875.2 v2(1877.53,1875.2)
  Bottom Layer w5: R185.1@1262.72,3200 v1(1290,3200) R175.1@1317.29,3200 ; v2(1877.53,1875.2) 1893.24,1859.49 U27.P1@1893.38,1859.49
ETH_TX_EN: R161.1 U27.P3 | length 371.6
  L3_SIG w4: v1(1835.52,2145) 1850,2145 1910.81,2084.19 1910.81,1969.2 1925,1955.01 1925,1890.72 v2(1940.52,1875.2)
  Bottom Layer w5: R161.1@1835,2172.28 1835,2145.52 v1(1835.52,2145) ; v2(1940.52,1875.2) 1956.23,1859.49 U27.P3@1956.37,1859.49
ETH_TXD0: R162.1 U27.T1 | length 329.1
  L3_SIG w4: v1(1795.52,2145.52) 1816.04,2125 1850,2125 1900,2075 1900,1960.68 v2(1877.53,1938.21)
  Bottom Layer w5: R162.1@1795,2172.28 1795,2146.04 v1(1795.52,2145.52) ; v2(1877.53,1938.21) 1893.26,1922.48 U27.T1@1893.38,1922.48
ETH_TXD1: R166.1 U27.R2 | length 413.8
  L3_SIG w4: v1(1755.52,2145.52) 1788.04,2113 1839.6,2113 1887.9,2064.7 1887.9,1975.6 1863.47,1951.17 1863.47,1932.47 1871.73,1924.21 1888.32,1924.21 1905.82,1906.71 v2(1909.02,1906.71)
  Bottom Layer w5: R166.1@1755,2172.28 1755,2146.04 v1(1755.52,2145.52) ; v2(1909.02,1906.71) 1924.74,1890.99 U27.R2@1924.88,1890.99
ETH_TXD2: R169.1 U27.R1 | length 416.9
  L3_SIG w4: v1(1715,2145) 1759,2101 1833.9,2101 1872.4,2062.5 1872.4,1980.2 1850.9,1958.7 1850.9,1933.33 v2(1877.52,1906.71)
  Bottom Layer w5: v1(1715,2145) R169.1@1715,2172.28 ; v2(1877.52,1906.71) 1893.24,1890.99 U27.R1@1893.38,1890.99
ETH_TXD3: R172.1 U27.P2 | length 460.2
  L3_SIG w4: v1(1675.52,2145) 1725,2095.52 1725,1989.99 1746.74,1968.25 1801.74,1968.25 1863.52,1906.47 1863.52,1900.91 1871.72,1892.71 1891.52,1892.71 v2(1909.03,1875.2)
  Bottom Layer w5: R172.1@1675,2172.28 1675,2145.52 v1(1675.52,2145) ; v2(1909.03,1875.2) 1924.74,1859.49 U27.P2@1924.88,1859.49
